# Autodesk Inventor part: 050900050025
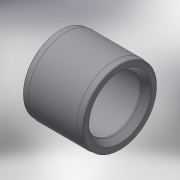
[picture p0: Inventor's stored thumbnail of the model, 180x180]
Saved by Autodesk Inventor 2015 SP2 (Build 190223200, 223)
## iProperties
Created: 2017-11
Part Number: 050900050025
Material: Generic
Description: PLASSON BUSHING-CEMENT PVC 50-25
Document SubType Name: Modeling
Designer: KIM
Density: 1 g/cm^3
Appearance: Default
Author: KIM
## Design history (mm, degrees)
derived "050900.ipt"
feature "Solid1::050900.ipt"
tag "TaggingFeature1"
body "Solid1"
other parameters: "d0" = 25, "d2" = 19, "d3" = 31, "d7" = 3.1, "d11" = 3.1, "d12" = 0.5, "d14" = 0.5, "d15" = 3.1, "d17" = 0.5, "d18" = 0.5, "d19" = 22.25, "d20" = 2.4, "d21" = 8.325, "d_" = 25, "L_" = 31, "l_" = 19, "z_" = 2
